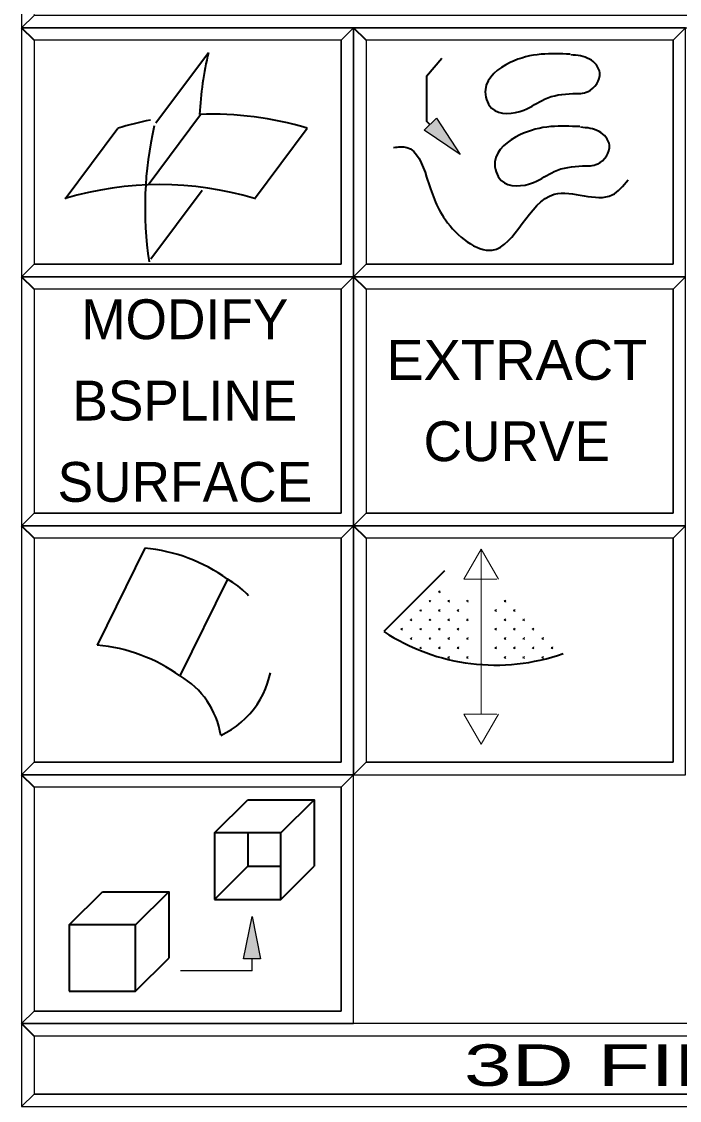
# Model space of a CAD drawing. Extents: x 95906.9 to 95918.9, y 90964.8 to 90972.9.
# Drawn here: x 95914.53 to 95915.322, y 90966.869 to 90968.169 of the extents above; entities that cross this region are included whole.
import ezdxf
from ezdxf.enums import TextEntityAlignment as Align

# ---------------------------------------------------------------- set-up
doc = ezdxf.new("R2010")
doc.units = 0
doc.header["$LTSCALE"] = 0.019
doc.linetypes.add('MEDIUM_DASHED', pattern=[4.5, 3, -1.5])
for name, color, linetype, lineweight in [('1', 7, 'Continuous', 25), ('11', 7, 'Continuous', 25), ('18', 7, 'Continuous', 25), ('2', 7, 'Continuous', 13), ('3', 7, 'Continuous', 25), ('4', 7, 'Continuous', 35), ('6', 7, 'Continuous', 35), ('7', 7, 'Continuous', 35)]:
    doc.layers.add(name, color=color, linetype=linetype, lineweight=lineweight)

msp = doc.modelspace()

# ---------------------------------------------------------------- hatches: boundary and pattern name
at = {"layer": '6'}
for points in [[(95915.0295, 90968.0527), (95915.058, 90968.0089), (95915.0149, 90968.0384)], [(95914.7973, 90967.0397), (95914.8075, 90967.0909), (95914.8177, 90967.0397)]]:
    msp.add_hatch(color=256, dxfattribs=at).paths.add_polyline_path(points)

# ---------------------------------------------------------------- linework, layer by layer
at = {"layer": '1'}
for points in [[(95914.5298, 90968.1617), (95916.1298, 90968.1617), (95916.1298, 90968.2617), (95914.5298, 90968.2617)], [(95914.5298, 90967.8617), (95914.9298, 90967.8617), (95914.9298, 90968.1617), (95914.5298, 90968.1617)], [(95914.9298, 90967.8617), (95915.3298, 90967.8617), (95915.3298, 90968.1617), (95914.9298, 90968.1617)], [(95914.5298, 90967.5617), (95914.9298, 90967.5617), (95914.9298, 90967.8617), (95914.5298, 90967.8617)], [(95914.9298, 90967.5617), (95915.3298, 90967.5617), (95915.3298, 90967.8617), (95914.9298, 90967.8617)], [(95914.5298, 90967.2617), (95914.9298, 90967.2617), (95914.9298, 90967.5617), (95914.5298, 90967.5617)], [(95914.9298, 90967.2617), (95915.3298, 90967.2617), (95915.3298, 90967.5617), (95914.9298, 90967.5617)], [(95914.5298, 90966.9617), (95914.9298, 90966.9617), (95914.9298, 90967.2617), (95914.5298, 90967.2617)], [(95914.5298, 90966.8617), (95916.1298, 90966.8617), (95916.1298, 90966.9617), (95914.5298, 90966.9617)]]:
    msp.add_lwpolyline(points, close=True, dxfattribs=at)
at = {"layer": '11'}
for points in [[(95914.5448, 90967.8767), (95914.9148, 90967.8767), (95914.9148, 90968.1467), (95914.5448, 90968.1467)], [(95914.9448, 90967.8767), (95915.3148, 90967.8767), (95915.3148, 90968.1467), (95914.9448, 90968.1467)], [(95914.5448, 90967.5767), (95914.9148, 90967.5767), (95914.9148, 90967.8467), (95914.5448, 90967.8467)], [(95914.9448, 90967.5767), (95915.3148, 90967.5767), (95915.3148, 90967.8467), (95914.9448, 90967.8467)], [(95914.5448, 90967.2767), (95914.9148, 90967.2767), (95914.9148, 90967.5467), (95914.5448, 90967.5467)], [(95914.9448, 90967.2767), (95915.3148, 90967.2767), (95915.3148, 90967.5467), (95914.9448, 90967.5467)], [(95914.5448, 90966.9767), (95914.9148, 90966.9767), (95914.9148, 90967.2467), (95914.5448, 90967.2467)]]:
    msp.add_lwpolyline(points, close=True, dxfattribs=at)
at = {"layer": '18'}
msp.add_lwpolyline([(95914.5448, 90966.8767), (95916.1148, 90966.8767), (95916.1148, 90966.9467), (95914.5448, 90966.9467)], close=True, dxfattribs=at)
at = {"layer": '2'}
for points in [[(95914.5298, 90968.2617), (95914.5298, 90968.1617), (95914.5448, 90968.1767), (95914.5448, 90968.2467), (95916.1148, 90968.2467), (95916.1298, 90968.2617)], [(95914.5298, 90968.1617), (95914.5298, 90967.8617), (95914.5448, 90967.8767), (95914.5448, 90968.1467), (95914.9148, 90968.1467), (95914.9298, 90968.1617)], [(95914.9298, 90968.1617), (95914.9298, 90967.8617), (95914.9448, 90967.8767), (95914.9448, 90968.1467), (95915.3148, 90968.1467), (95915.3298, 90968.1617)], [(95914.5298, 90967.8617), (95914.5298, 90967.5617), (95914.5448, 90967.5767), (95914.5448, 90967.8467), (95914.9148, 90967.8467), (95914.9298, 90967.8617)], [(95914.9298, 90967.8617), (95914.9298, 90967.5617), (95914.9448, 90967.5767), (95914.9448, 90967.8467), (95915.3148, 90967.8467), (95915.3298, 90967.8617)], [(95914.5298, 90967.5617), (95914.5298, 90967.2617), (95914.5448, 90967.2767), (95914.5448, 90967.5467), (95914.9148, 90967.5467), (95914.9298, 90967.5617)], [(95914.9298, 90967.5617), (95914.9298, 90967.2617), (95914.9448, 90967.2767), (95914.9448, 90967.5467), (95915.3148, 90967.5467), (95915.3298, 90967.5617)], [(95914.5298, 90967.2617), (95914.5298, 90966.9617), (95914.5448, 90966.9767), (95914.5448, 90967.2467), (95914.9148, 90967.2467), (95914.9298, 90967.2617)], [(95914.5298, 90966.9617), (95914.5298, 90966.8617), (95914.5448, 90966.8767), (95914.5448, 90966.9467), (95916.1148, 90966.9467), (95916.1298, 90966.9617)]]:
    msp.add_lwpolyline(points, close=True, dxfattribs=at)
at = {"layer": '3'}
for points in [[(95914.5298, 90968.1617), (95916.1298, 90968.1617), (95916.1298, 90968.2617), (95916.1148, 90968.2467), (95916.1148, 90968.1767), (95914.5448, 90968.1767)], [(95914.5298, 90967.8617), (95914.9298, 90967.8617), (95914.9298, 90968.1617), (95914.9148, 90968.1467), (95914.9148, 90967.8767), (95914.5448, 90967.8767)], [(95914.9298, 90967.8617), (95915.3298, 90967.8617), (95915.3298, 90968.1617), (95915.3148, 90968.1467), (95915.3148, 90967.8767), (95914.9448, 90967.8767)], [(95914.5298, 90967.5617), (95914.9298, 90967.5617), (95914.9298, 90967.8617), (95914.9148, 90967.8467), (95914.9148, 90967.5767), (95914.5448, 90967.5767)], [(95914.9298, 90967.5617), (95915.3298, 90967.5617), (95915.3298, 90967.8617), (95915.3148, 90967.8467), (95915.3148, 90967.5767), (95914.9448, 90967.5767)], [(95914.5298, 90967.2617), (95914.9298, 90967.2617), (95914.9298, 90967.5617), (95914.9148, 90967.5467), (95914.9148, 90967.2767), (95914.5448, 90967.2767)], [(95914.9298, 90967.2617), (95915.3298, 90967.2617), (95915.3298, 90967.5617), (95915.3148, 90967.5467), (95915.3148, 90967.2767), (95914.9448, 90967.2767)], [(95914.5298, 90966.9617), (95914.9298, 90966.9617), (95914.9298, 90967.2617), (95914.9148, 90967.2467), (95914.9148, 90966.9767), (95914.5448, 90966.9767)], [(95914.5298, 90966.8617), (95916.1298, 90966.8617), (95916.1298, 90966.9617), (95916.1148, 90966.9467), (95916.1148, 90966.8767), (95914.5448, 90966.8767)]]:
    msp.add_lwpolyline(points, close=True, dxfattribs=at)
at = {"layer": '4'}
for p, q in [((95914.5448, 90968.1467), (95914.5298, 90968.1617)), ((95914.9448, 90968.1467), (95914.9298, 90968.1617)), ((95914.5448, 90967.8467), (95914.5298, 90967.8617)), ((95914.9448, 90967.8467), (95914.9298, 90967.8617)), ((95914.5448, 90967.5467), (95914.5298, 90967.5617)), ((95914.9448, 90967.5467), (95914.9298, 90967.5617)), ((95914.5448, 90967.2467), (95914.5298, 90967.2617)), ((95914.5448, 90966.9467), (95914.5298, 90966.9617))]:
    msp.add_line(p, q, dxfattribs=at)
at = {"layer": '6'}
for p, q in [((95914.6916, 90968.0471), (95914.7549, 90968.1319)), ((95914.6821, 90967.9726), (95914.7454, 90968.0574)), ((95914.5825, 90967.9558), (95914.6458, 90968.0406)), ((95914.8105, 90967.9558), (95914.8738, 90968.0406)), ((95914.6855, 90967.8833), (95914.7473, 90967.9661)), ((95914.6783, 90967.5346), (95914.621, 90967.4179)), ((95915.0394, 90967.5074), (95914.9663, 90967.4343)), ((95914.7779, 90967.4974), (95914.7206, 90967.3807)), ((95915.0325, 90967.4822), (95915.0332, 90967.483)), ((95915.0332, 90967.4815), (95915.0325, 90967.4822)), ((95915.0339, 90967.4822), (95915.0332, 90967.483)), ((95915.0332, 90967.4815), (95915.0339, 90967.4822)), ((95915.0212, 90967.4709), (95915.0219, 90967.4716)), ((95915.0219, 90967.4702), (95915.0212, 90967.4709)), ((95915.0226, 90967.4709), (95915.0219, 90967.4716)), ((95915.0219, 90967.4702), (95915.0226, 90967.4709)), ((95915.0438, 90967.4709), (95915.0445, 90967.4716)), ((95915.0445, 90967.4702), (95915.0438, 90967.4709)), ((95915.0452, 90967.4709), (95915.0445, 90967.4716)), ((95915.0445, 90967.4702), (95915.0452, 90967.4709)), ((95915.0664, 90967.4709), (95915.0671, 90967.4716)), ((95915.0671, 90967.4702), (95915.0664, 90967.4709)), ((95915.0679, 90967.4709), (95915.0671, 90967.4716)), ((95915.0671, 90967.4702), (95915.0679, 90967.4709)), ((95915.1117, 90967.4709), (95915.1124, 90967.4716)), ((95915.1124, 90967.4702), (95915.1117, 90967.4709)), ((95915.1131, 90967.4709), (95915.1124, 90967.4716)), ((95915.1124, 90967.4702), (95915.1131, 90967.4709)), ((95914.9986, 90967.4483), (95914.9993, 90967.449)), ((95914.9993, 90967.4476), (95914.9986, 90967.4483)), ((95915, 90967.4483), (95914.9993, 90967.449)), ((95914.9993, 90967.4476), (95915, 90967.4483)), ((95915.0099, 90967.4596), (95915.0106, 90967.4603)), ((95915.0106, 90967.4589), (95915.0099, 90967.4596)), ((95915.0113, 90967.4596), (95915.0106, 90967.4603)), ((95915.0106, 90967.4589), (95915.0113, 90967.4596)), ((95915.0212, 90967.4483), (95915.0219, 90967.449)), ((95915.0219, 90967.4476), (95915.0212, 90967.4483)), ((95915.0226, 90967.4483), (95915.0219, 90967.449)), ((95915.0219, 90967.4476), (95915.0226, 90967.4483)), ((95915.0325, 90967.4596), (95915.0332, 90967.4603)), ((95915.0332, 90967.4589), (95915.0325, 90967.4596)), ((95915.0339, 90967.4596), (95915.0332, 90967.4603)), ((95915.0332, 90967.4589), (95915.0339, 90967.4596)), ((95915.0438, 90967.4483), (95915.0445, 90967.449)), ((95915.0445, 90967.4476), (95915.0438, 90967.4483)), ((95915.0452, 90967.4483), (95915.0445, 90967.449)), ((95915.0445, 90967.4476), (95915.0452, 90967.4483)), ((95915.0551, 90967.4596), (95915.0558, 90967.4603)), ((95915.0558, 90967.4589), (95915.0551, 90967.4596)), ((95915.0565, 90967.4596), (95915.0558, 90967.4603)), ((95915.0558, 90967.4589), (95915.0565, 90967.4596)), ((95915.0664, 90967.4483), (95915.0671, 90967.449)), ((95915.0671, 90967.4476), (95915.0664, 90967.4483)), ((95915.0679, 90967.4483), (95915.0671, 90967.449)), ((95915.0671, 90967.4476), (95915.0679, 90967.4483)), ((95915.1004, 90967.4596), (95915.1011, 90967.4603)), ((95915.1011, 90967.4589), (95915.1004, 90967.4596)), ((95915.1018, 90967.4596), (95915.1011, 90967.4603)), ((95915.1011, 90967.4589), (95915.1018, 90967.4596)), ((95915.1117, 90967.4483), (95915.1124, 90967.449)), ((95915.1124, 90967.4476), (95915.1117, 90967.4483)), ((95915.1131, 90967.4483), (95915.1124, 90967.449)), ((95915.1124, 90967.4476), (95915.1131, 90967.4483)), ((95915.123, 90967.4596), (95915.1237, 90967.4603)), ((95915.1237, 90967.4589), (95915.123, 90967.4596)), ((95915.1244, 90967.4596), (95915.1237, 90967.4603)), ((95915.1237, 90967.4589), (95915.1244, 90967.4596)), ((95915.1343, 90967.4483), (95915.135, 90967.449)), ((95915.135, 90967.4476), (95915.1343, 90967.4483)), ((95915.1357, 90967.4483), (95915.135, 90967.449)), ((95915.135, 90967.4476), (95915.1357, 90967.4483)), ((95914.9872, 90967.437), (95914.9879, 90967.4377)), ((95914.9879, 90967.4363), (95914.9872, 90967.437)), ((95914.9887, 90967.437), (95914.9879, 90967.4377)), ((95914.9879, 90967.4363), (95914.9887, 90967.437)), ((95915.0099, 90967.437), (95915.0106, 90967.4377)), ((95915.0106, 90967.4363), (95915.0099, 90967.437)), ((95915.0113, 90967.437), (95915.0106, 90967.4377)), ((95915.0106, 90967.4363), (95915.0113, 90967.437)), ((95915.0325, 90967.437), (95915.0332, 90967.4377)), ((95915.0332, 90967.4363), (95915.0325, 90967.437)), ((95915.0339, 90967.437), (95915.0332, 90967.4377)), ((95915.0332, 90967.4363), (95915.0339, 90967.437)), ((95915.0551, 90967.437), (95915.0558, 90967.4377)), ((95915.0558, 90967.4363), (95915.0551, 90967.437)), ((95915.0565, 90967.437), (95915.0558, 90967.4377)), ((95915.0558, 90967.4363), (95915.0565, 90967.437)), ((95915.1004, 90967.437), (95915.1011, 90967.4377)), ((95915.1011, 90967.4363), (95915.1004, 90967.437)), ((95915.1018, 90967.437), (95915.1011, 90967.4377)), ((95915.1011, 90967.4363), (95915.1018, 90967.437)), ((95915.123, 90967.437), (95915.1237, 90967.4377)), ((95915.1237, 90967.4363), (95915.123, 90967.437)), ((95915.1244, 90967.437), (95915.1237, 90967.4377)), ((95915.1237, 90967.4363), (95915.1244, 90967.437)), ((95915.1456, 90967.437), (95915.1463, 90967.4377)), ((95915.1463, 90967.4363), (95915.1456, 90967.437)), ((95915.147, 90967.437), (95915.1463, 90967.4377)), ((95915.1463, 90967.4363), (95915.147, 90967.437)), ((95914.9986, 90967.4257), (95914.9993, 90967.4264)), ((95914.9993, 90967.425), (95914.9986, 90967.4257)), ((95915, 90967.4257), (95914.9993, 90967.4264)), ((95914.9993, 90967.425), (95915, 90967.4257)), ((95915.0212, 90967.4257), (95915.0219, 90967.4264)), ((95915.0219, 90967.425), (95915.0212, 90967.4257)), ((95915.0226, 90967.4257), (95915.0219, 90967.4264)), ((95915.0219, 90967.425), (95915.0226, 90967.4257)), ((95915.0438, 90967.4257), (95915.0445, 90967.4264)), ((95915.0445, 90967.425), (95915.0438, 90967.4257)), ((95915.0452, 90967.4257), (95915.0445, 90967.4264)), ((95915.0445, 90967.425), (95915.0452, 90967.4257)), ((95915.0664, 90967.4257), (95915.0671, 90967.4264)), ((95915.0671, 90967.425), (95915.0664, 90967.4257)), ((95915.0679, 90967.4257), (95915.0671, 90967.4264)), ((95915.0671, 90967.425), (95915.0679, 90967.4257)), ((95915.1117, 90967.4257), (95915.1124, 90967.4264)), ((95915.1124, 90967.425), (95915.1117, 90967.4257)), ((95915.1131, 90967.4257), (95915.1124, 90967.4264)), ((95915.1124, 90967.425), (95915.1131, 90967.4257)), ((95915.1343, 90967.4257), (95915.135, 90967.4264)), ((95915.135, 90967.425), (95915.1343, 90967.4257)), ((95915.1357, 90967.4257), (95915.135, 90967.4264)), ((95915.135, 90967.425), (95915.1357, 90967.4257)), ((95915.1569, 90967.4257), (95915.1577, 90967.4264)), ((95915.1577, 90967.425), (95915.1569, 90967.4257)), ((95915.1584, 90967.4257), (95915.1577, 90967.4264)), ((95915.1577, 90967.425), (95915.1584, 90967.4257)), ((95915.0099, 90967.4144), (95915.0106, 90967.4151)), ((95915.0106, 90967.4137), (95915.0099, 90967.4144)), ((95915.0113, 90967.4144), (95915.0106, 90967.4151)), ((95915.0106, 90967.4137), (95915.0113, 90967.4144)), ((95915.0325, 90967.4144), (95915.0332, 90967.4151)), ((95915.0332, 90967.4137), (95915.0325, 90967.4144)), ((95915.0339, 90967.4144), (95915.0332, 90967.4151)), ((95915.0332, 90967.4137), (95915.0339, 90967.4144)), ((95915.0551, 90967.4144), (95915.0558, 90967.4151)), ((95915.0558, 90967.4137), (95915.0551, 90967.4144)), ((95915.0565, 90967.4144), (95915.0558, 90967.4151)), ((95915.0558, 90967.4137), (95915.0565, 90967.4144)), ((95915.1004, 90967.4144), (95915.1011, 90967.4151)), ((95915.1011, 90967.4137), (95915.1004, 90967.4144)), ((95915.1018, 90967.4144), (95915.1011, 90967.4151)), ((95915.1011, 90967.4137), (95915.1018, 90967.4144)), ((95915.123, 90967.4144), (95915.1237, 90967.4151)), ((95915.1237, 90967.4137), (95915.123, 90967.4144)), ((95915.1244, 90967.4144), (95915.1237, 90967.4151)), ((95915.1237, 90967.4137), (95915.1244, 90967.4144)), ((95915.1456, 90967.4144), (95915.1463, 90967.4151)), ((95915.1463, 90967.4137), (95915.1456, 90967.4144)), ((95915.147, 90967.4144), (95915.1463, 90967.4151)), ((95915.1463, 90967.4137), (95915.147, 90967.4144)), ((95915.1683, 90967.4144), (95915.169, 90967.4151)), ((95915.169, 90967.4137), (95915.1683, 90967.4144)), ((95915.1697, 90967.4144), (95915.169, 90967.4151)), ((95915.169, 90967.4137), (95915.1697, 90967.4144)), ((95915.0438, 90967.4031), (95915.0445, 90967.4038)), ((95915.0445, 90967.4023), (95915.0438, 90967.4031)), ((95915.0452, 90967.4031), (95915.0445, 90967.4038)), ((95915.0445, 90967.4023), (95915.0452, 90967.4031)), ((95915.0664, 90967.4031), (95915.0671, 90967.4038)), ((95915.0671, 90967.4023), (95915.0664, 90967.4031)), ((95915.0679, 90967.4031), (95915.0671, 90967.4038)), ((95915.0671, 90967.4023), (95915.0679, 90967.4031)), ((95915.1117, 90967.4031), (95915.1124, 90967.4038)), ((95915.1124, 90967.4023), (95915.1117, 90967.4031)), ((95915.1131, 90967.4031), (95915.1124, 90967.4038)), ((95915.1124, 90967.4023), (95915.1131, 90967.4031)), ((95915.1343, 90967.4031), (95915.135, 90967.4038)), ((95915.135, 90967.4023), (95915.1343, 90967.4031)), ((95915.1357, 90967.4031), (95915.135, 90967.4038)), ((95915.135, 90967.4023), (95915.1357, 90967.4031)), ((95915.1569, 90967.4031), (95915.1577, 90967.4038)), ((95915.1577, 90967.4023), (95915.1569, 90967.4031)), ((95915.1584, 90967.4031), (95915.1577, 90967.4038)), ((95915.1577, 90967.4023), (95915.1584, 90967.4031)), ((95914.7622, 90967.1915), (95914.8022, 90967.2315)), ((95914.8422, 90967.1915), (95914.8822, 90967.2315)), ((95914.7622, 90967.1115), (95914.8022, 90967.1515)), ((95914.8422, 90967.1115), (95914.8822, 90967.1515)), ((95914.5872, 90967.0807), (95914.6272, 90967.1207)), ((95914.6672, 90967.0807), (95914.7072, 90967.1207)), ((95914.6672, 90967.0007), (95914.7072, 90967.0407))]:
    msp.add_line(p, q, dxfattribs=at)
at = {"layer": '6', "lineweight": 13}
for p, q in [((95915.0836, 90967.433), (95915.0836, 90967.5335)), ((95915.0627, 90967.4975), (95915.1023, 90967.4975))]:
    msp.add_line(p, q, dxfattribs=at)
at = {"layer": '6', "linetype": 'MEDIUM_DASHED', "lineweight": 13}
for p, q in [((95915.0836, 90967.3345), (95915.0836, 90967.433)), ((95915.0627, 90967.3345), (95915.1023, 90967.3345))]:
    msp.add_line(p, q, dxfattribs=at)
at = {"layer": '6', "lineweight": 25}
for p, q in [((95914.8177, 90967.0397), (95914.7973, 90967.0397)), ((95914.8075, 90967.0252), (95914.8075, 90967.0397)), ((95914.8075, 90967.0252), (95914.7211, 90967.0252))]:
    msp.add_line(p, q, dxfattribs=at)
at = {"layer": '6'}
for points in [[(95915.0361, 90968.1247), (95915.0178, 90968.1031), (95915.0178, 90968.0491), (95915.0218, 90968.045)], [(95914.8022, 90967.2315), (95914.8822, 90967.2315), (95914.8822, 90967.1515)], [(95914.8022, 90967.1915), (95914.8022, 90967.1515), (95914.8422, 90967.1515)], [(95914.6272, 90967.1207), (95914.7072, 90967.1207), (95914.7072, 90967.0407)]]:
    msp.add_lwpolyline(points, dxfattribs=at)
at = {"layer": '6', "lineweight": 25}
for points in [[(95915.0295, 90968.0527), (95915.058, 90968.0089), (95915.0149, 90968.0384)], [(95914.7973, 90967.0397), (95914.8075, 90967.0909), (95914.8177, 90967.0397)]]:
    msp.add_lwpolyline(points, close=True, dxfattribs=at)
at = {"layer": '6', "lineweight": 13}
msp.add_lwpolyline([(95915.1044, 90967.4975), (95915.0836, 90967.5335), (95915.0627, 90967.4975)], dxfattribs=at)
at = {"layer": '6', "linetype": 'MEDIUM_DASHED', "lineweight": 13}
msp.add_lwpolyline([(95915.1044, 90967.3345), (95915.0836, 90967.2985), (95915.0627, 90967.3345)], dxfattribs=at)
at = {"layer": '6'}
for points in [[(95914.7622, 90967.1115), (95914.8422, 90967.1115), (95914.8422, 90967.1915), (95914.7622, 90967.1915)], [(95914.5872, 90967.0007), (95914.6672, 90967.0007), (95914.6672, 90967.0807), (95914.5872, 90967.0807)]]:
    msp.add_lwpolyline(points, close=True, dxfattribs=at)
for centre, radius, start, end in [((95915.1809, 90968.0341), 0.4372, 167.0623, 176.9616), ((95914.7598, 90967.6651), 0.3925, 100.9847, 106.8869), ((95914.7598, 90967.6651), 0.3925, 73.1131, 92.2503), ((95915.1157, 90967.9456), 0.4372, 167.0622, 188.6792), ((95914.6965, 90967.5803), 0.3925, 73.1131, 106.8869), ((95914.6599, 90967.3333), 0.2021, 54.27, 84.7693), ((95915.1009, 90967.6379), 0.2441, 236.5268, 289.4193), ((95914.6026, 90967.2166), 0.2021, 54.27, 84.7615)]:
    msp.add_arc(centre, radius, start, end, dxfattribs=at)
at = {"layer": '6', "linetype": 'MEDIUM_DASHED'}
for centre, radius, start, end in [((95914.7259, 90967.4053), 0.1057, 294.5009, 60.5562), ((95914.6697, 90967.2931), 0.1014, 9.108, 59.8295)]:
    msp.add_arc(centre, radius, start, end, dxfattribs=at)
at = {"layer": '6'}
for points in [[(95915.1907, 90968.1298), (95915.1558, 90968.1298), (95915.1184, 90968.1198), (95915.0885, 90968.0874), (95915.096, 90968.065), (95915.135, 90968.0625), (95915.1599, 90968.0758), (95915.194, 90968.0824), (95915.2123, 90968.0849), (95915.2264, 90968.1074), (95915.2139, 90968.124), (95915.1915, 90968.129)], [(95915.2023, 90968.0426), (95915.1674, 90968.0426), (95915.13, 90968.0326), (95915.1001, 90968.0002), (95915.1076, 90967.9778), (95915.1466, 90967.9753), (95915.1715, 90967.9886), (95915.2056, 90967.9952), (95915.2239, 90967.9977), (95915.238, 90968.0202), (95915.2255, 90968.0368), (95915.2031, 90968.0418)], [(95914.978, 90968.0176), (95914.9938, 90968.0176), (95915.0178, 90967.9819), (95915.0403, 90967.9304), (95915.0968, 90967.8938), (95915.1716, 90967.9611), (95915.2414, 90967.9603), (95915.2605, 90967.9786)]]:
    msp.add_spline(points, degree=3, dxfattribs=at)

# ---------------------------------------------------------------- texts
for s, p in [('MODIFY', (95914.7264, 90967.7865)), ('BSPLINE', (95914.7265, 90967.6885)), ('CURVE', (95915.1264, 90967.6395)), ('SURFACE', (95914.7265, 90967.5905))]:
    msp.add_text(s, height=0.048, dxfattribs=at).set_placement(p, align=Align.CENTER)
at = {"layer": '6', "width": 1.05}
msp.add_text('EXTRACT', height=0.048, dxfattribs=at).set_placement((95915.1264, 90967.7375), align=Align.CENTER)
at = {"layer": '7', "width": 1.55}
msp.add_text('      3D FILLETS    ', height=0.05, dxfattribs=at).set_placement((95915.3189, 90966.8867), align=Align.CENTER)

doc.saveas('drawing.dxf')
